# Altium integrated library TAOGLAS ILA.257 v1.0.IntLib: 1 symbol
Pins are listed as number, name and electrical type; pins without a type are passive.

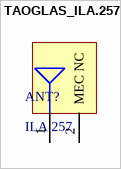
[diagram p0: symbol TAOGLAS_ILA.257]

## TAOGLAS_ILA.257
designator ANT?, comment ILA.257
LTCC Wi-Fi 6/7 Chip Antenna Covering 2.4/5/7GHz; ComponentLibStatus: Created; MFG: Taoglas; Temp_High: +85C; Temp_Low: -40C
footprint TAOGLAS_ILA.257 (LTCC Wi-Fi 6/7 Chip Antenna Covering 2.4/5/7GHz)
pins: 1 RF OUT, 2 MEC NC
